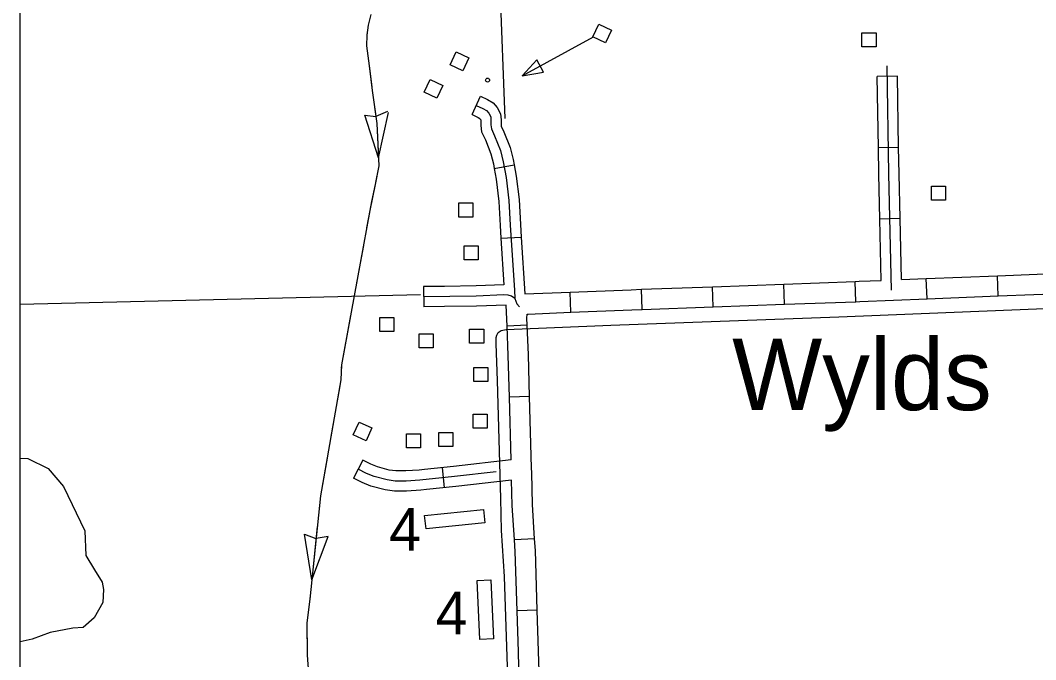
# Model space of a CAD drawing. Extents: x 155 to 3386, y 68 to 2138.
# Drawn here: x 1150.5 to 1365.4, y 802.6 to 937.9 of the extents above; entities that cross this region are included whole.
import ezdxf

# ---------------------------------------------------------------- set-up
doc = ezdxf.new("R2010")
doc.units = 0
for name, color, linetype in [('Default', 7, 'Continuous'), ('E_No Plot', 7, 'Continuous'), ('Level 24', 7, 'Continuous'), ('Level 32', 7, 'Continuous'), ('Level 4', 7, 'Continuous'), ('Level 43', 7, 'Continuous'), ('Level 47', 7, 'Continuous'), ('Level 5', 7, 'Continuous'), ('Level 56', 7, 'Continuous')]:
    doc.layers.add(name, color=color, linetype=linetype)

msp = doc.modelspace()

# ---------------------------------------------------------------- linework, layer by layer
at = {"layer": 'Default'}
msp.add_lwpolyline([(1150.5, 1308.99), (2342.15, 1308.99), (2342.15, 348.58), (1150.5, 348.58)], close=True, dxfattribs=at)
at = {"layer": 'E_No Plot'}
msp.add_lwpolyline([(1150.5, 1308.99), (2342.15, 1308.99), (2342.15, 348.58), (1150.5, 348.58)], close=True, dxfattribs=at)
msp.add_lwpolyline([(1150.5, 1308.99), (2342.15, 1308.99), (2342.15, 348.58), (1150.5, 348.58)], close=True, dxfattribs=at)
at = {"layer": 'Level 32'}
for p, q in [((1336.13, 926.12), (1331.85, 926.05)), ((1246.09, 917.98), (1247.9, 921.87)), ((1336.38, 911.04), (1332.09, 910.97)), ((1250.8, 906.56), (1255.02, 907.32)), ((1336.68, 895.97), (1332.4, 895.87)), ((1252.22, 891.8), (1256.5, 892.08)), ((1342.39, 879), (1342.22, 883.28)), ((1357.47, 879.61), (1357.29, 883.89)), ((1235.81, 881.58), (1235.86, 877.3)), ((1297.16, 877.28), (1297, 881.56)), ((1312.24, 877.84), (1312.08, 882.12)), ((1327.31, 878.39), (1327.15, 882.68)), ((1267.02, 876.14), (1266.85, 880.42)), ((1282.09, 876.72), (1281.93, 881.01)), ((1257.78, 873.41), (1253.5, 873.24)), ((1258.28, 858.31), (1254, 858.19)), ((1239.74, 843.28), (1240.2, 839)), ((1259.34, 828.24), (1255.06, 827.96)), ((1259.91, 813.1), (1255.63, 812.96))]:
    msp.add_line(p, q, dxfattribs=at)
for points in [[(1334.89, 880.84), (1334.32, 905.44), (1333.95, 928.33)], [(1332.09, 910.97), (1331.85, 926.05)], [(1336.38, 911.04), (1336.13, 926.12)], [(1247.9, 921.87), (1249.38, 921.18), (1250.57, 920.48), (1251.4, 919.49), (1252.15, 918.15), (1252.23, 916.85), (1252.23, 915.93), (1252.27, 915.54), (1252.83, 914.37), (1254.16, 911.04), (1254.81, 908.47), (1255.02, 907.32)], [(1247, 919.93), (1248.38, 919.28), (1249.16, 918.82), (1249.62, 918.26), (1250.04, 917.53), (1250.09, 916.79), (1250.09, 915.82), (1250.18, 914.94), (1250.87, 913.51), (1252.11, 910.37), (1252.71, 908.02), (1253.31, 904.65), (1253.91, 899.81), (1254.19, 894.62), (1255.07, 880.83), (1255.16, 879.07), (1255.34, 878.47), (1255.57, 877.96), (1256.14, 877.31)], [(1246.09, 917.98), (1247.38, 917.38), (1247.75, 917.16), (1247.85, 917.04), (1247.93, 916.9), (1247.94, 916.72), (1247.94, 915.71), (1248.09, 914.35), (1248.91, 912.65), (1250.07, 909.71), (1250.62, 907.57), (1250.8, 906.56)], [(1332.4, 895.87), (1332.18, 905.4), (1332.09, 910.97)], [(1336.68, 895.97), (1336.46, 905.48), (1336.38, 911.04)], [(1255.02, 907.32), (1255.43, 904.97), (1256.05, 900), (1256.33, 894.75), (1256.5, 892.08)], [(1250.8, 906.56), (1251.19, 904.33), (1251.78, 899.62), (1252.05, 894.5), (1252.22, 891.8)], [(1332.7, 882.9), (1332.4, 895.87)], [(1336.98, 883.07), (1336.68, 895.97)], [(1252.22, 891.8), (1252.85, 881.96)], [(1256.5, 892.08), (1257.26, 880.04)], [(1336.98, 883.07), (1342.22, 883.28)], [(1342.22, 883.28), (1357.29, 883.89)], [(1357.29, 883.89), (1372.37, 884.5)], [(1240.24, 881.64), (1235.81, 881.58)], [(1252.85, 881.96), (1246.94, 881.72), (1240.24, 881.64)], [(1281.93, 881.01), (1297, 881.56)], [(1297, 881.56), (1312.08, 882.12)], [(1312.08, 882.12), (1327.15, 882.68)], [(1327.15, 882.68), (1328.03, 882.71), (1332.7, 882.9)], [(1255.16, 879.07), (1254.47, 879.58), (1253.77, 879.76), (1252.81, 879.81), (1246.99, 879.58), (1235.83, 879.44)], [(1257.26, 880.04), (1266.85, 880.42)], [(1266.85, 880.42), (1279.76, 880.93), (1281.93, 881.01)], [(1327.31, 878.39), (1328.19, 878.43), (1342.39, 879)], [(1342.39, 879), (1357.47, 879.61)], [(1357.47, 879.61), (1372.54, 880.21)], [(1240.3, 877.35), (1235.86, 877.3)], [(1253.32, 877.69), (1247.05, 877.44), (1240.3, 877.35)], [(1253.65, 798.99), (1252.97, 820.26), (1252.33, 829.95), (1252.19, 836.72), (1251.5, 861.68), (1251.19, 869.5), (1251.23, 870.83), (1251.32, 871.29), (1251.64, 871.84), (1252.24, 872.29), (1253.33, 872.52), (1275.45, 873.39), (1323.72, 875.17), (1372.53, 877.14)], [(1253.5, 873.24), (1253.32, 877.69)], [(1282.09, 876.72), (1297.16, 877.28)], [(1297.16, 877.28), (1312.24, 877.84)], [(1312.24, 877.84), (1327.31, 878.39)], [(1257.78, 873.41), (1257.72, 874.9), (1257.75, 875.73), (1257.99, 875.78), (1267.02, 876.14)], [(1267.02, 876.14), (1279.93, 876.64), (1282.09, 876.72)], [(1254, 858.19), (1253.76, 867.01), (1253.5, 873.24)], [(1258.28, 858.31), (1258.04, 867.15), (1257.78, 873.41)], [(1254.36, 844.94), (1254, 858.19)], [(1258.7, 843.23), (1258.28, 858.31)], [(1236.01, 842.88), (1234.89, 842.76), (1232.1, 842.58), (1230, 842.58), (1228.53, 842.77), (1226.07, 843.44), (1224.67, 844), (1223.02, 844.87), (1221.02, 841.08)], [(1254.36, 844.94), (1242.17, 843.54), (1236.01, 842.88)], [(1251.23, 842.42), (1242.41, 841.41), (1235.07, 840.62), (1232.17, 840.44), (1229.86, 840.44), (1228.11, 840.67), (1225.39, 841.41), (1223.77, 842.05), (1222.02, 842.98)], [(1259.34, 828.24), (1258.86, 835.44), (1258.73, 842.16), (1258.7, 843.23)], [(1236.46, 838.62), (1235.25, 838.49), (1232.23, 838.3), (1229.72, 838.3), (1227.69, 838.56), (1224.71, 839.37), (1222.87, 840.1), (1221.02, 841.08)], [(1254.47, 840.64), (1242.64, 839.28), (1236.46, 838.62)], [(1255.06, 827.96), (1254.58, 835.25), (1254.47, 840.64)], [(1255.63, 812.96), (1255.22, 825.55), (1255.06, 827.96)], [(1259.91, 813.1), (1259.5, 825.76), (1259.34, 828.24)], [(1256.09, 797.89), (1255.9, 804.32), (1255.63, 812.96)], [(1260.37, 798.01), (1260.19, 804.45), (1259.91, 813.1)]]:
    msp.add_lwpolyline(points, dxfattribs=at)
at = {"layer": 'Level 4'}
msp.add_lwpolyline([(1248.81, 1028.41), (1253.05, 917.17)], dxfattribs=at)
at = {"layer": 'Level 43'}
for p, q in [((1223.41, 917.89), (1225.74, 917.6)), ((1226.31, 908.83), (1223.41, 917.89)), ((1228.17, 918.63), (1225.77, 917.61)), ((1226.31, 908.83), (1228.39, 918.42)), ((1212.16, 819.54), (1210.62, 829.22)), ((1210.62, 829.22), (1213.06, 828.29)), ((1212.16, 819.54), (1215.67, 828.7)), ((1215.67, 828.7), (1213.09, 828.28))]:
    msp.add_line(p, q, dxfattribs=at)
for points in [[(1224.7, 939.17), (1224.08, 936.93), (1223.83, 934.83), (1223.76, 932.52), (1224.33, 928.3), (1224.98, 923.1), (1225.96, 916.13), (1226.39, 907.17), (1225.6, 903.2), (1224.44, 897.69), (1222.42, 886.53), (1218.45, 865.04), (1218.31, 861.82), (1214.01, 837.3), (1211.74, 815.45), (1211.12, 810.43), (1211.23, 803.6), (1211.92, 794.11)], [(1223.86, 935.07), (1223.83, 934.83), (1223.76, 932.52), (1224.33, 928.3), (1224.89, 923.84)], [(1225.4, 920.1), (1225.96, 916.13), (1226.31, 908.83)], [(1225.98, 905.1), (1225.6, 903.2), (1224.84, 899.56)], [(1224.84, 899.56), (1224.44, 897.69), (1223.78, 894.01)], [(1223.1, 890.3), (1222.42, 886.53), (1221.57, 881.93)], [(1220.38, 875.46), (1218.45, 865.04), (1218.42, 864.32)], [(1218.09, 860.57), (1216.13, 849.43)], [(1215.48, 845.71), (1214.01, 837.3), (1213.72, 834.54)], [(1213.33, 830.79), (1212.16, 819.54)], [(1211.77, 815.79), (1211.74, 815.45), (1211.12, 810.43), (1211.13, 810.17)], [(1211.13, 810.17), (1211.22, 804.51)]]:
    msp.add_lwpolyline(points, dxfattribs=at)
at = {"layer": 'Level 47'}
for points in [[(1150.5, 845.29), (1152.1, 845.18), (1156.38, 843.1), (1159.62, 839.28)], [(1159.62, 839.28), (1164.14, 829.9), (1164.37, 824.69), (1166.22, 821.68), (1167.84, 819.02), (1168.07, 817.51), (1167.96, 814.73), (1166.11, 811.49), (1163.79, 809.41), (1161.59, 809.29), (1156.85, 808.36), (1153.03, 806.98), (1150.5, 806.41)]]:
    msp.add_lwpolyline(points, dxfattribs=at)
at = {"layer": 'Level 5'}
msp.add_lwpolyline([(1150.5, 877.87), (1235.16, 879.94)], dxfattribs=at)
at = {"layer": 'Level 56'}
for points in [[(1274.35, 933.15), (1271.66, 934.41), (1272.92, 937.11), (1275.61, 935.86)], [(1328.61, 932.33), (1328.61, 935.3), (1331.59, 935.3), (1331.59, 932.33)], [(1244.14, 927.28), (1241.45, 928.54), (1242.71, 931.24), (1245.4, 929.98)], [(1261.23, 926.99), (1259.83, 929.54), (1256.7, 926.16)], [(1238.66, 921.45), (1235.97, 922.71), (1237.23, 925.41), (1239.93, 924.15)], [(1343.34, 899.88), (1343.34, 902.85), (1346.33, 902.85), (1346.33, 899.88)], [(1243.31, 896.31), (1243.31, 899.29), (1246.29, 899.29), (1246.29, 896.31)], [(1244.44, 887.24), (1244.44, 890.22), (1247.42, 890.22), (1247.42, 887.24)], [(1226.58, 872.06), (1226.58, 875.04), (1229.57, 875.04), (1229.57, 872.06)], [(1245.59, 869.63), (1245.59, 872.6), (1248.58, 872.6), (1248.58, 869.63)], [(1234.91, 868.61), (1234.91, 871.58), (1237.89, 871.58), (1237.89, 868.61)], [(1246.45, 861.48), (1246.45, 864.45), (1249.44, 864.45), (1249.44, 861.48)], [(1246.31, 851.63), (1246.31, 854.6), (1249.29, 854.6), (1249.29, 851.63)], [(1223.68, 848.96), (1220.97, 850.2), (1222.22, 852.91), (1224.92, 851.67)], [(1232.22, 847.49), (1232.22, 850.46), (1235.2, 850.46), (1235.2, 847.49)], [(1239.06, 847.76), (1239.06, 850.74), (1242.04, 850.74), (1242.04, 847.76)], [(1248.5, 834.44), (1248.79, 831.59), (1236.36, 830.29), (1236.06, 833.13)], [(1250.63, 807.05), (1247.78, 806.91), (1247.2, 819.4), (1250.05, 819.53)]]:
    msp.add_lwpolyline(points, close=True, dxfattribs=at)
msp.add_lwpolyline([(1256.7, 926.16), (1271.78, 934.46)], dxfattribs=at)
msp.add_circle((1249.38, 925.28), 0.429, dxfattribs=at)

# ---------------------------------------------------------------- texts
at = {"layer": 'Level 24'}
msp.add_text('Wylds', height=15.086, dxfattribs=at).set_placement((1301.16, 855.45))
at = {"layer": 'Level 56'}
for p in [(1228.56, 825.67), (1238.4, 808.01)]:
    msp.add_text('4', height=9.05, dxfattribs=at).set_placement(p)

doc.saveas('drawing.dxf')
